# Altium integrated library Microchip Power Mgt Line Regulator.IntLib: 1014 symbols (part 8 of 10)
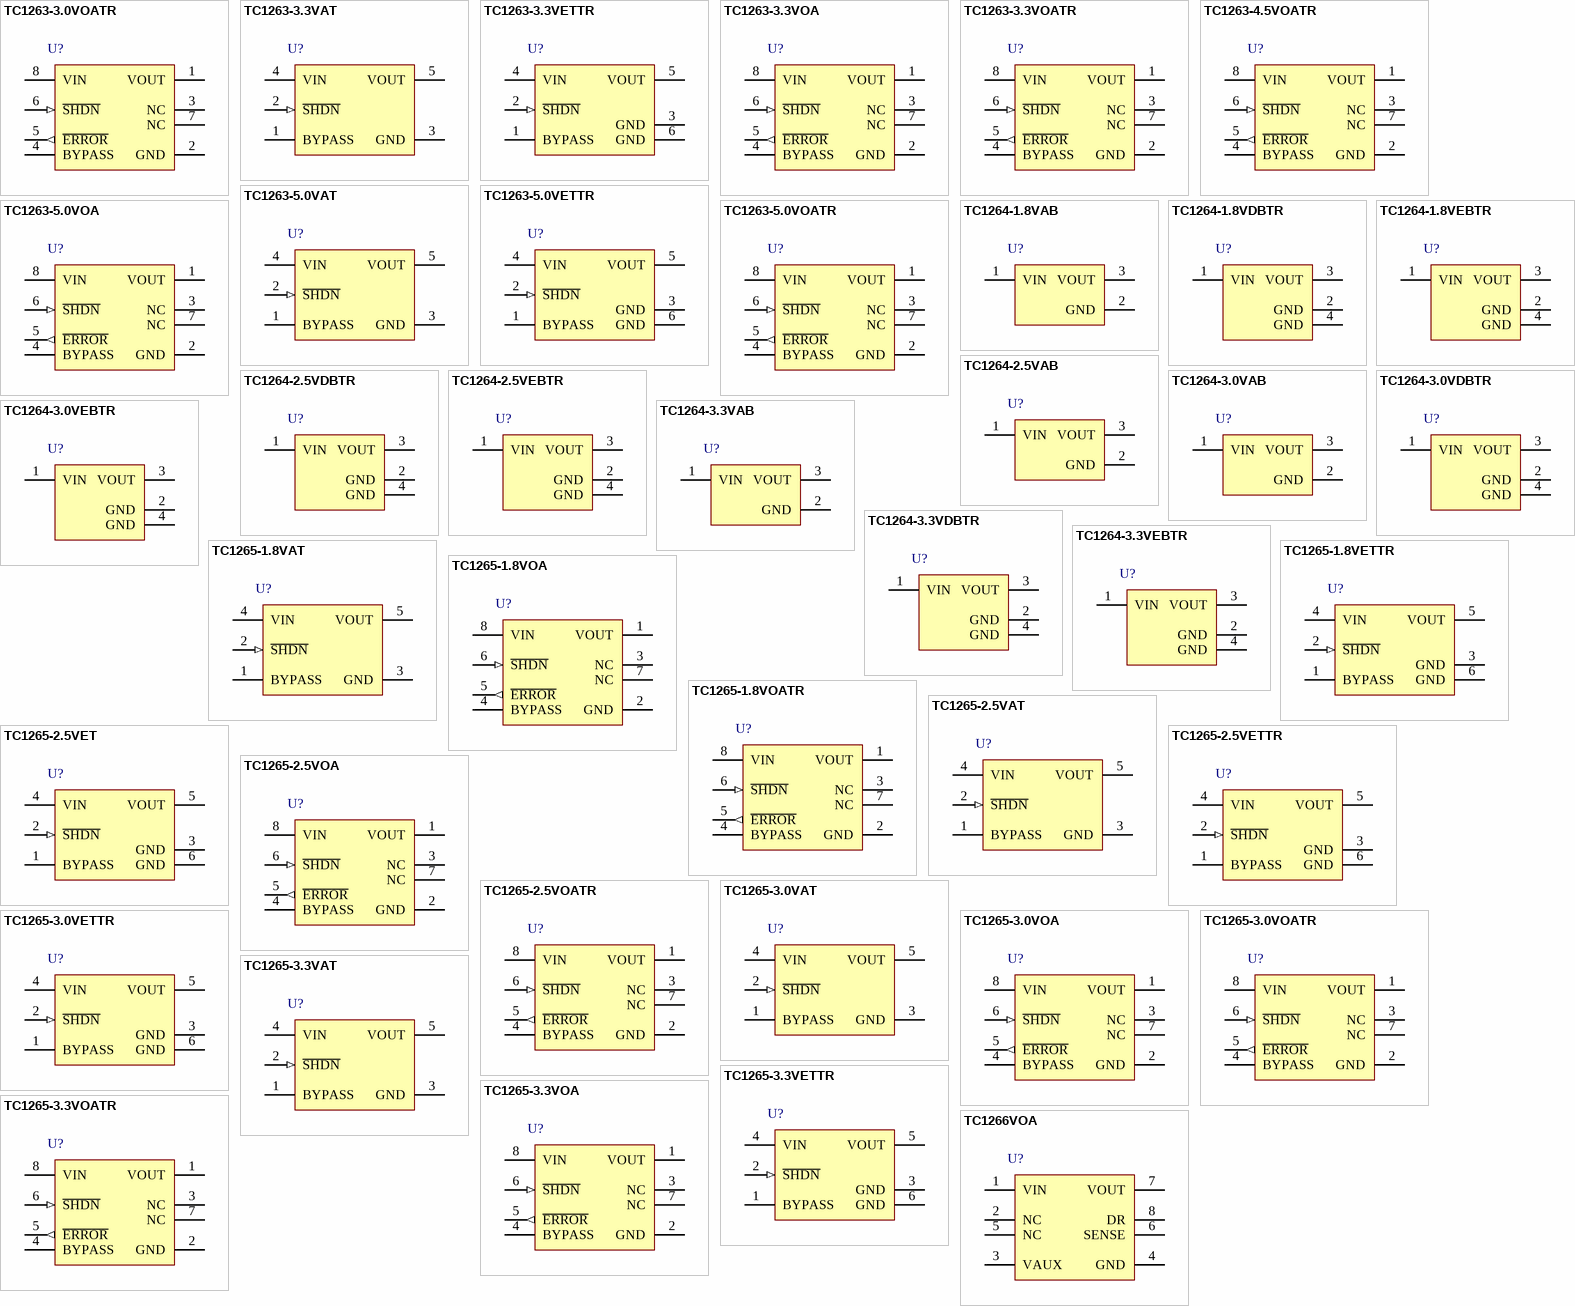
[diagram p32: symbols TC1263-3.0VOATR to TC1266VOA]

## TC1263-3.3VOA
designator U?
500mA Fixed Output, CMOS LDO with Shutdown, 8-Pin SOIC 150mil, Extended Temperature
footprint SOIC-OA8_N (SOIC, 8-Leads, Body 4.9x3.9mm, Pitch 1.27mm, IPC Medium Density)
footprint SOIC-OA8_L (SOIC, 8-Leads, Body 4.9x3.9mm, Pitch 1.27mm, IPC High Density)
footprint SOIC-OA8_M (SOIC, 8-Leads, Body 4.9x3.9mm, Pitch 1.27mm, IPC Low Density)
pins: 1 VOUT (power), 2 GND (power), 3 NC, 4 BYPASS, 5 ~{ERROR} (out), 6 ~{SHDN} (in), 7 NC, 8 VIN (power)

## TC1263-3.3VOATR
designator U?
500mA Fixed Output, CMOS LDO with Shutdown, 8-Pin SOIC 150mil, Extended Temperature, Tape and Reel
footprint SOIC-OA8_N (SOIC, 8-Leads, Body 4.9x3.9mm, Pitch 1.27mm, IPC Medium Density)
footprint SOIC-OA8_L (SOIC, 8-Leads, Body 4.9x3.9mm, Pitch 1.27mm, IPC High Density)
footprint SOIC-OA8_M (SOIC, 8-Leads, Body 4.9x3.9mm, Pitch 1.27mm, IPC Low Density)
pins: 1 VOUT (power), 2 GND (power), 3 NC, 4 BYPASS, 5 ~{ERROR} (out), 6 ~{SHDN} (in), 7 NC, 8 VIN (power)

## TC1263-4.5VOATR
designator U?
500mA Fixed Output, CMOS LDO with Shutdown, 8-Pin SOIC 150mil, Extended Temperature, Tape and Reel
footprint SOIC-OA8_N (SOIC, 8-Leads, Body 4.9x3.9mm, Pitch 1.27mm, IPC Medium Density)
footprint SOIC-OA8_L (SOIC, 8-Leads, Body 4.9x3.9mm, Pitch 1.27mm, IPC High Density)
footprint SOIC-OA8_M (SOIC, 8-Leads, Body 4.9x3.9mm, Pitch 1.27mm, IPC Low Density)
pins: 1 VOUT (power), 2 GND (power), 3 NC, 4 BYPASS, 5 ~{ERROR} (out), 6 ~{SHDN} (in), 7 NC, 8 VIN (power)

## TC1263-5.0VAT
designator U?
500mA Fixed Output, CMOS LDO with Shutdown, 5-Pin TO-220, Extended Temperature
footprint TO-220-AT5 (TO, Thru-Hole, Vertical, Heatsink Mounted; 5 In-Line Leads; Pitch 1.70 mm)
pins: 1 BYPASS, 2 ~{SHDN} (in), 3 GND (power), 4 VIN (power), 5 VOUT (power)

## TC1263-5.0VETTR
designator U?
500mA Fixed Output, CMOS LDO with Shutdown, 5-Pin DDPAK, Extended Temperature, Tape and Reel
footprint DDPAK-ET5_N (D2-PAK, 6-Leads, Body 9x10.2mm, Pitch 1.7mm, Lead Span 14.9mm, IPC Medium Density)
footprint DDPAK-ET5_L (D2-PAK, 6-Leads, Body 9x10.2mm, Pitch 1.7mm, Lead Span 14.9mm, IPC High Density)
footprint DDPAK-ET5_M (D2-PAK, 6-Leads, Body 9x10.2mm, Pitch 1.7mm, Lead Span 14.9mm, IPC Low Density)
pins: 1 BYPASS, 2 ~{SHDN} (in), 3 GND (power), 4 VIN (power), 5 VOUT (power), 6 GND (power)

## TC1263-5.0VOA
designator U?
500mA Fixed Output, CMOS LDO with Shutdown, 8-Pin SOIC 150mil, Extended Temperature
footprint SOIC-OA8_N (SOIC, 8-Leads, Body 4.9x3.9mm, Pitch 1.27mm, IPC Medium Density)
footprint SOIC-OA8_L (SOIC, 8-Leads, Body 4.9x3.9mm, Pitch 1.27mm, IPC High Density)
footprint SOIC-OA8_M (SOIC, 8-Leads, Body 4.9x3.9mm, Pitch 1.27mm, IPC Low Density)
pins: 1 VOUT (power), 2 GND (power), 3 NC, 4 BYPASS, 5 ~{ERROR} (out), 6 ~{SHDN} (in), 7 NC, 8 VIN (power)

## TC1263-5.0VOATR
designator U?
500mA Fixed Output, CMOS LDO with Shutdown, 8-Pin SOIC 150mil, Extended Temperature, Tape and Reel
footprint SOIC-OA8_N (SOIC, 8-Leads, Body 4.9x3.9mm, Pitch 1.27mm, IPC Medium Density)
footprint SOIC-OA8_L (SOIC, 8-Leads, Body 4.9x3.9mm, Pitch 1.27mm, IPC High Density)
footprint SOIC-OA8_M (SOIC, 8-Leads, Body 4.9x3.9mm, Pitch 1.27mm, IPC Low Density)
pins: 1 VOUT (power), 2 GND (power), 3 NC, 4 BYPASS, 5 ~{ERROR} (out), 6 ~{SHDN} (in), 7 NC, 8 VIN (power)

## TC1264-1.8VAB
designator U?
800 mA Fixed-Output CMOS LDO with Shutdown, 3-Pin TO-220, Extended Temperature
footprint TO-220-AB3 (TO, Thru-Hole, Vertical, Heatsink Mounted; 3 In-Line Leads; Pitch 2.54 mm)
pins: 1 VIN (power), 2 GND (power), 3 VOUT (power)

## TC1264-1.8VDBTR
designator U?
800 mA Fixed-Output CMOS LDO with Shutdown, 3-Pin SOT-223, Extended Temperature, Tape and Reel
footprint SOT-223-DB3_N (SOT223, 4-Leads, Body 6.5x3.5mm, Pitch 2.3mm, Lead Span 7mm, IPC Medium Density)
footprint SOT-223-DB3_L (SOT223, 4-Leads, Body 6.5x3.5mm, Pitch 2.3mm, Lead Span 7mm, IPC High Density)
footprint SOT-223-DB3_M (SOT223, 4-Leads, Body 6.5x3.5mm, Pitch 2.3mm, Lead Span 7mm, IPC Low Density)
pins: 1 VIN (power), 2 GND (power), 3 VOUT (power), 4 GND (power)

## TC1264-1.8VEBTR
designator U?
800 mA Fixed-Output CMOS LDO with Shutdown, 3-Pin DDPAK, Extended Temperature, Tape and Reel
footprint DDPAK-EB3_N (D2-PAK, 4-Leads, Body 9x10.2mm, Pitch 2.54mm, Lead Span 14.9mm, IPC Medium Density)
footprint DDPAK-EB3_L (D2-PAK, 4-Leads, Body 9x10.2mm, Pitch 2.54mm, Lead Span 14.9mm, IPC High Density)
footprint DDPAK-EB3_M (D2-PAK, 4-Leads, Body 9x10.2mm, Pitch 2.54mm, Lead Span 14.9mm, IPC Low Density)
pins: 1 VIN (power), 2 GND (power), 3 VOUT (power), 4 GND (power)

## TC1264-2.5VAB
designator U?
800 mA Fixed-Output CMOS LDO with Shutdown, 3-Pin TO-220, Extended Temperature
footprint TO-220-AB3 (TO, Thru-Hole, Vertical, Heatsink Mounted; 3 In-Line Leads; Pitch 2.54 mm)
pins: 1 VIN (power), 2 GND (power), 3 VOUT (power)

## TC1264-2.5VDBTR
designator U?
800 mA Fixed-Output CMOS LDO with Shutdown, 3-Pin SOT-223, Extended Temperature, Tape and Reel
footprint SOT-223-DB3_N (SOT223, 4-Leads, Body 6.5x3.5mm, Pitch 2.3mm, Lead Span 7mm, IPC Medium Density)
footprint SOT-223-DB3_L (SOT223, 4-Leads, Body 6.5x3.5mm, Pitch 2.3mm, Lead Span 7mm, IPC High Density)
footprint SOT-223-DB3_M (SOT223, 4-Leads, Body 6.5x3.5mm, Pitch 2.3mm, Lead Span 7mm, IPC Low Density)
pins: 1 VIN (power), 2 GND (power), 3 VOUT (power), 4 GND (power)

## TC1264-2.5VEBTR
designator U?
800 mA Fixed-Output CMOS LDO with Shutdown, 3-Pin DDPAK, Extended Temperature, Tape and Reel
footprint DDPAK-EB3_N (D2-PAK, 4-Leads, Body 9x10.2mm, Pitch 2.54mm, Lead Span 14.9mm, IPC Medium Density)
footprint DDPAK-EB3_L (D2-PAK, 4-Leads, Body 9x10.2mm, Pitch 2.54mm, Lead Span 14.9mm, IPC High Density)
footprint DDPAK-EB3_M (D2-PAK, 4-Leads, Body 9x10.2mm, Pitch 2.54mm, Lead Span 14.9mm, IPC Low Density)
pins: 1 VIN (power), 2 GND (power), 3 VOUT (power), 4 GND (power)

## TC1264-3.0VAB
designator U?
800 mA Fixed-Output CMOS LDO with Shutdown, 3-Pin TO-220, Extended Temperature
footprint TO-220-AB3 (TO, Thru-Hole, Vertical, Heatsink Mounted; 3 In-Line Leads; Pitch 2.54 mm)
pins: 1 VIN (power), 2 GND (power), 3 VOUT (power)

## TC1264-3.0VDBTR
designator U?
800 mA Fixed-Output CMOS LDO with Shutdown, 3-Pin SOT-223, Extended Temperature, Tape and Reel
footprint SOT-223-DB3_N (SOT223, 4-Leads, Body 6.5x3.5mm, Pitch 2.3mm, Lead Span 7mm, IPC Medium Density)
footprint SOT-223-DB3_L (SOT223, 4-Leads, Body 6.5x3.5mm, Pitch 2.3mm, Lead Span 7mm, IPC High Density)
footprint SOT-223-DB3_M (SOT223, 4-Leads, Body 6.5x3.5mm, Pitch 2.3mm, Lead Span 7mm, IPC Low Density)
pins: 1 VIN (power), 2 GND (power), 3 VOUT (power), 4 GND (power)

## TC1264-3.0VEBTR
designator U?
800 mA Fixed-Output CMOS LDO with Shutdown, 3-Pin DDPAK, Extended Temperature, Tape and Reel
footprint DDPAK-EB3_N (D2-PAK, 4-Leads, Body 9x10.2mm, Pitch 2.54mm, Lead Span 14.9mm, IPC Medium Density)
footprint DDPAK-EB3_L (D2-PAK, 4-Leads, Body 9x10.2mm, Pitch 2.54mm, Lead Span 14.9mm, IPC High Density)
footprint DDPAK-EB3_M (D2-PAK, 4-Leads, Body 9x10.2mm, Pitch 2.54mm, Lead Span 14.9mm, IPC Low Density)
pins: 1 VIN (power), 2 GND (power), 3 VOUT (power), 4 GND (power)

## TC1264-3.3VAB
designator U?
800 mA Fixed-Output CMOS LDO with Shutdown, 3-Pin TO-220, Extended Temperature
footprint TO-220-AB3 (TO, Thru-Hole, Vertical, Heatsink Mounted; 3 In-Line Leads; Pitch 2.54 mm)
pins: 1 VIN (power), 2 GND (power), 3 VOUT (power)

## TC1264-3.3VDBTR
designator U?
800 mA Fixed-Output CMOS LDO with Shutdown, 3-Pin SOT-223, Extended Temperature, Tape and Reel
footprint SOT-223-DB3_N (SOT223, 4-Leads, Body 6.5x3.5mm, Pitch 2.3mm, Lead Span 7mm, IPC Medium Density)
footprint SOT-223-DB3_L (SOT223, 4-Leads, Body 6.5x3.5mm, Pitch 2.3mm, Lead Span 7mm, IPC High Density)
footprint SOT-223-DB3_M (SOT223, 4-Leads, Body 6.5x3.5mm, Pitch 2.3mm, Lead Span 7mm, IPC Low Density)
pins: 1 VIN (power), 2 GND (power), 3 VOUT (power), 4 GND (power)

## TC1264-3.3VEBTR
designator U?
800 mA Fixed-Output CMOS LDO with Shutdown, 3-Pin DDPAK, Extended Temperature, Tape and Reel
footprint DDPAK-EB3_N (D2-PAK, 4-Leads, Body 9x10.2mm, Pitch 2.54mm, Lead Span 14.9mm, IPC Medium Density)
footprint DDPAK-EB3_L (D2-PAK, 4-Leads, Body 9x10.2mm, Pitch 2.54mm, Lead Span 14.9mm, IPC High Density)
footprint DDPAK-EB3_M (D2-PAK, 4-Leads, Body 9x10.2mm, Pitch 2.54mm, Lead Span 14.9mm, IPC Low Density)
pins: 1 VIN (power), 2 GND (power), 3 VOUT (power), 4 GND (power)

## TC1265-1.8VAT
designator U?
800 mA Fixed-Output CMOS LDO with Shutdown, 5-Pin TO-220, Extended Temperature
footprint TO-220-AT5 (TO, Thru-Hole, Vertical, Heatsink Mounted; 5 In-Line Leads; Pitch 1.70 mm)
pins: 1 BYPASS, 2 ~{SHDN} (in), 3 GND (power), 4 VIN (power), 5 VOUT (power)

## TC1265-1.8VETTR
designator U?
800 mA Fixed-Output CMOS LDO with Shutdown, 5-Pin DDPAK, Extended Temperature, Tape and Reel
footprint DDPAK-ET5_N (D2-PAK, 6-Leads, Body 9x10.2mm, Pitch 1.7mm, Lead Span 14.9mm, IPC Medium Density)
footprint DDPAK-ET5_L (D2-PAK, 6-Leads, Body 9x10.2mm, Pitch 1.7mm, Lead Span 14.9mm, IPC High Density)
footprint DDPAK-ET5_M (D2-PAK, 6-Leads, Body 9x10.2mm, Pitch 1.7mm, Lead Span 14.9mm, IPC Low Density)
pins: 1 BYPASS, 2 ~{SHDN} (in), 3 GND (power), 4 VIN (power), 5 VOUT (power), 6 GND (power)

## TC1265-1.8VOA
designator U?
800 mA Fixed-Output CMOS LDO with Shutdown, 8-Pin SOIC 150mil, Extended Temperature
footprint SOIC-OA8_N (SOIC, 8-Leads, Body 4.9x3.9mm, Pitch 1.27mm, IPC Medium Density)
footprint SOIC-OA8_L (SOIC, 8-Leads, Body 4.9x3.9mm, Pitch 1.27mm, IPC High Density)
footprint SOIC-OA8_M (SOIC, 8-Leads, Body 4.9x3.9mm, Pitch 1.27mm, IPC Low Density)
pins: 1 VOUT (power), 2 GND (power), 3 NC, 4 BYPASS, 5 ~{ERROR} (out), 6 ~{SHDN} (in), 7 NC, 8 VIN (power)

## TC1265-1.8VOATR
designator U?
800 mA Fixed-Output CMOS LDO with Shutdown, 8-Pin SOIC 150mil, Extended Temperature, Tape and Reel
footprint SOIC-OA8_N (SOIC, 8-Leads, Body 4.9x3.9mm, Pitch 1.27mm, IPC Medium Density)
footprint SOIC-OA8_L (SOIC, 8-Leads, Body 4.9x3.9mm, Pitch 1.27mm, IPC High Density)
footprint SOIC-OA8_M (SOIC, 8-Leads, Body 4.9x3.9mm, Pitch 1.27mm, IPC Low Density)
pins: 1 VOUT (power), 2 GND (power), 3 NC, 4 BYPASS, 5 ~{ERROR} (out), 6 ~{SHDN} (in), 7 NC, 8 VIN (power)

## TC1265-2.5VAT
designator U?
800 mA Fixed-Output CMOS LDO with Shutdown, 5-Pin TO-220, Extended Temperature
footprint TO-220-AT5 (TO, Thru-Hole, Vertical, Heatsink Mounted; 5 In-Line Leads; Pitch 1.70 mm)
pins: 1 BYPASS, 2 ~{SHDN} (in), 3 GND (power), 4 VIN (power), 5 VOUT (power)

## TC1265-2.5VET
designator U?
800 mA Fixed-Output CMOS LDO with Shutdown, 5-Pin DDPAK, Extended Temperature
footprint DDPAK-ET5_N (D2-PAK, 6-Leads, Body 9x10.2mm, Pitch 1.7mm, Lead Span 14.9mm, IPC Medium Density)
footprint DDPAK-ET5_L (D2-PAK, 6-Leads, Body 9x10.2mm, Pitch 1.7mm, Lead Span 14.9mm, IPC High Density)
footprint DDPAK-ET5_M (D2-PAK, 6-Leads, Body 9x10.2mm, Pitch 1.7mm, Lead Span 14.9mm, IPC Low Density)
pins: 1 BYPASS, 2 ~{SHDN} (in), 3 GND (power), 4 VIN (power), 5 VOUT (power), 6 GND (power)

## TC1265-2.5VETTR
designator U?
800 mA Fixed-Output CMOS LDO with Shutdown, 5-Pin DDPAK, Extended Temperature, Tape and Reel
footprint DDPAK-ET5_N (D2-PAK, 6-Leads, Body 9x10.2mm, Pitch 1.7mm, Lead Span 14.9mm, IPC Medium Density)
footprint DDPAK-ET5_L (D2-PAK, 6-Leads, Body 9x10.2mm, Pitch 1.7mm, Lead Span 14.9mm, IPC High Density)
footprint DDPAK-ET5_M (D2-PAK, 6-Leads, Body 9x10.2mm, Pitch 1.7mm, Lead Span 14.9mm, IPC Low Density)
pins: 1 BYPASS, 2 ~{SHDN} (in), 3 GND (power), 4 VIN (power), 5 VOUT (power), 6 GND (power)

## TC1265-2.5VOA
designator U?
800 mA Fixed-Output CMOS LDO with Shutdown, 8-Pin SOIC 150mil, Extended Temperature
footprint SOIC-OA8_N (SOIC, 8-Leads, Body 4.9x3.9mm, Pitch 1.27mm, IPC Medium Density)
footprint SOIC-OA8_L (SOIC, 8-Leads, Body 4.9x3.9mm, Pitch 1.27mm, IPC High Density)
footprint SOIC-OA8_M (SOIC, 8-Leads, Body 4.9x3.9mm, Pitch 1.27mm, IPC Low Density)
pins: 1 VOUT (power), 2 GND (power), 3 NC, 4 BYPASS, 5 ~{ERROR} (out), 6 ~{SHDN} (in), 7 NC, 8 VIN (power)

## TC1265-2.5VOATR
designator U?
800 mA Fixed-Output CMOS LDO with Shutdown, 8-Pin SOIC 150mil, Extended Temperature, Tape and Reel
footprint SOIC-OA8_N (SOIC, 8-Leads, Body 4.9x3.9mm, Pitch 1.27mm, IPC Medium Density)
footprint SOIC-OA8_L (SOIC, 8-Leads, Body 4.9x3.9mm, Pitch 1.27mm, IPC High Density)
footprint SOIC-OA8_M (SOIC, 8-Leads, Body 4.9x3.9mm, Pitch 1.27mm, IPC Low Density)
pins: 1 VOUT (power), 2 GND (power), 3 NC, 4 BYPASS, 5 ~{ERROR} (out), 6 ~{SHDN} (in), 7 NC, 8 VIN (power)

## TC1265-3.0VAT
designator U?
800 mA Fixed-Output CMOS LDO with Shutdown, 5-Pin TO-220, Extended Temperature
footprint TO-220-AT5 (TO, Thru-Hole, Vertical, Heatsink Mounted; 5 In-Line Leads; Pitch 1.70 mm)
pins: 1 BYPASS, 2 ~{SHDN} (in), 3 GND (power), 4 VIN (power), 5 VOUT (power)

## TC1265-3.0VETTR
designator U?
800 mA Fixed-Output CMOS LDO with Shutdown, 5-Pin DDPAK, Extended Temperature, Tape and Reel
footprint DDPAK-ET5_N (D2-PAK, 6-Leads, Body 9x10.2mm, Pitch 1.7mm, Lead Span 14.9mm, IPC Medium Density)
footprint DDPAK-ET5_L (D2-PAK, 6-Leads, Body 9x10.2mm, Pitch 1.7mm, Lead Span 14.9mm, IPC High Density)
footprint DDPAK-ET5_M (D2-PAK, 6-Leads, Body 9x10.2mm, Pitch 1.7mm, Lead Span 14.9mm, IPC Low Density)
pins: 1 BYPASS, 2 ~{SHDN} (in), 3 GND (power), 4 VIN (power), 5 VOUT (power), 6 GND (power)

## TC1265-3.0VOA
designator U?
800 mA Fixed-Output CMOS LDO with Shutdown, 8-Pin SOIC 150mil, Extended Temperature
footprint SOIC-OA8_N (SOIC, 8-Leads, Body 4.9x3.9mm, Pitch 1.27mm, IPC Medium Density)
footprint SOIC-OA8_L (SOIC, 8-Leads, Body 4.9x3.9mm, Pitch 1.27mm, IPC High Density)
footprint SOIC-OA8_M (SOIC, 8-Leads, Body 4.9x3.9mm, Pitch 1.27mm, IPC Low Density)
pins: 1 VOUT (power), 2 GND (power), 3 NC, 4 BYPASS, 5 ~{ERROR} (out), 6 ~{SHDN} (in), 7 NC, 8 VIN (power)

## TC1265-3.0VOATR
designator U?
800 mA Fixed-Output CMOS LDO with Shutdown, 8-Pin SOIC 150mil, Extended Temperature, Tape and Reel
footprint SOIC-OA8_N (SOIC, 8-Leads, Body 4.9x3.9mm, Pitch 1.27mm, IPC Medium Density)
footprint SOIC-OA8_L (SOIC, 8-Leads, Body 4.9x3.9mm, Pitch 1.27mm, IPC High Density)
footprint SOIC-OA8_M (SOIC, 8-Leads, Body 4.9x3.9mm, Pitch 1.27mm, IPC Low Density)
pins: 1 VOUT (power), 2 GND (power), 3 NC, 4 BYPASS, 5 ~{ERROR} (out), 6 ~{SHDN} (in), 7 NC, 8 VIN (power)

## TC1265-3.3VAT
designator U?
800 mA Fixed-Output CMOS LDO with Shutdown, 5-Pin TO-220, Extended Temperature
footprint TO-220-AT5 (TO, Thru-Hole, Vertical, Heatsink Mounted; 5 In-Line Leads; Pitch 1.70 mm)
pins: 1 BYPASS, 2 ~{SHDN} (in), 3 GND (power), 4 VIN (power), 5 VOUT (power)

## TC1265-3.3VETTR
designator U?
800 mA Fixed-Output CMOS LDO with Shutdown, 5-Pin DDPAK, Extended Temperature, Tape and Reel
footprint DDPAK-ET5_N (D2-PAK, 6-Leads, Body 9x10.2mm, Pitch 1.7mm, Lead Span 14.9mm, IPC Medium Density)
footprint DDPAK-ET5_L (D2-PAK, 6-Leads, Body 9x10.2mm, Pitch 1.7mm, Lead Span 14.9mm, IPC High Density)
footprint DDPAK-ET5_M (D2-PAK, 6-Leads, Body 9x10.2mm, Pitch 1.7mm, Lead Span 14.9mm, IPC Low Density)
pins: 1 BYPASS, 2 ~{SHDN} (in), 3 GND (power), 4 VIN (power), 5 VOUT (power), 6 GND (power)

## TC1265-3.3VOA
designator U?
800 mA Fixed-Output CMOS LDO with Shutdown, 8-Pin SOIC 150mil, Extended Temperature
footprint SOIC-OA8_N (SOIC, 8-Leads, Body 4.9x3.9mm, Pitch 1.27mm, IPC Medium Density)
footprint SOIC-OA8_L (SOIC, 8-Leads, Body 4.9x3.9mm, Pitch 1.27mm, IPC High Density)
footprint SOIC-OA8_M (SOIC, 8-Leads, Body 4.9x3.9mm, Pitch 1.27mm, IPC Low Density)
pins: 1 VOUT (power), 2 GND (power), 3 NC, 4 BYPASS, 5 ~{ERROR} (out), 6 ~{SHDN} (in), 7 NC, 8 VIN (power)

## TC1265-3.3VOATR
designator U?
800 mA Fixed-Output CMOS LDO with Shutdown, 8-Pin SOIC 150mil, Extended Temperature, Tape and Reel
footprint SOIC-OA8_N (SOIC, 8-Leads, Body 4.9x3.9mm, Pitch 1.27mm, IPC Medium Density)
footprint SOIC-OA8_L (SOIC, 8-Leads, Body 4.9x3.9mm, Pitch 1.27mm, IPC High Density)
footprint SOIC-OA8_M (SOIC, 8-Leads, Body 4.9x3.9mm, Pitch 1.27mm, IPC Low Density)
pins: 1 VOUT (power), 2 GND (power), 3 NC, 4 BYPASS, 5 ~{ERROR} (out), 6 ~{SHDN} (in), 7 NC, 8 VIN (power)

## TC1266VOA
designator U?
200mA PCI LDO, 8-Pin SOIC 150mil
footprint SOIC-OA8_N (SOIC, 8-Leads, Body 4.9x3.9mm, Pitch 1.27mm, IPC Medium Density)
footprint SOIC-OA8_L (SOIC, 8-Leads, Body 4.9x3.9mm, Pitch 1.27mm, IPC High Density)
footprint SOIC-OA8_M (SOIC, 8-Leads, Body 4.9x3.9mm, Pitch 1.27mm, IPC Low Density)
pins: 1 VIN (power), 2 NC, 3 VAUX (power), 4 GND (power), 5 NC, 6 SENSE, 7 VOUT (power), 8 DR

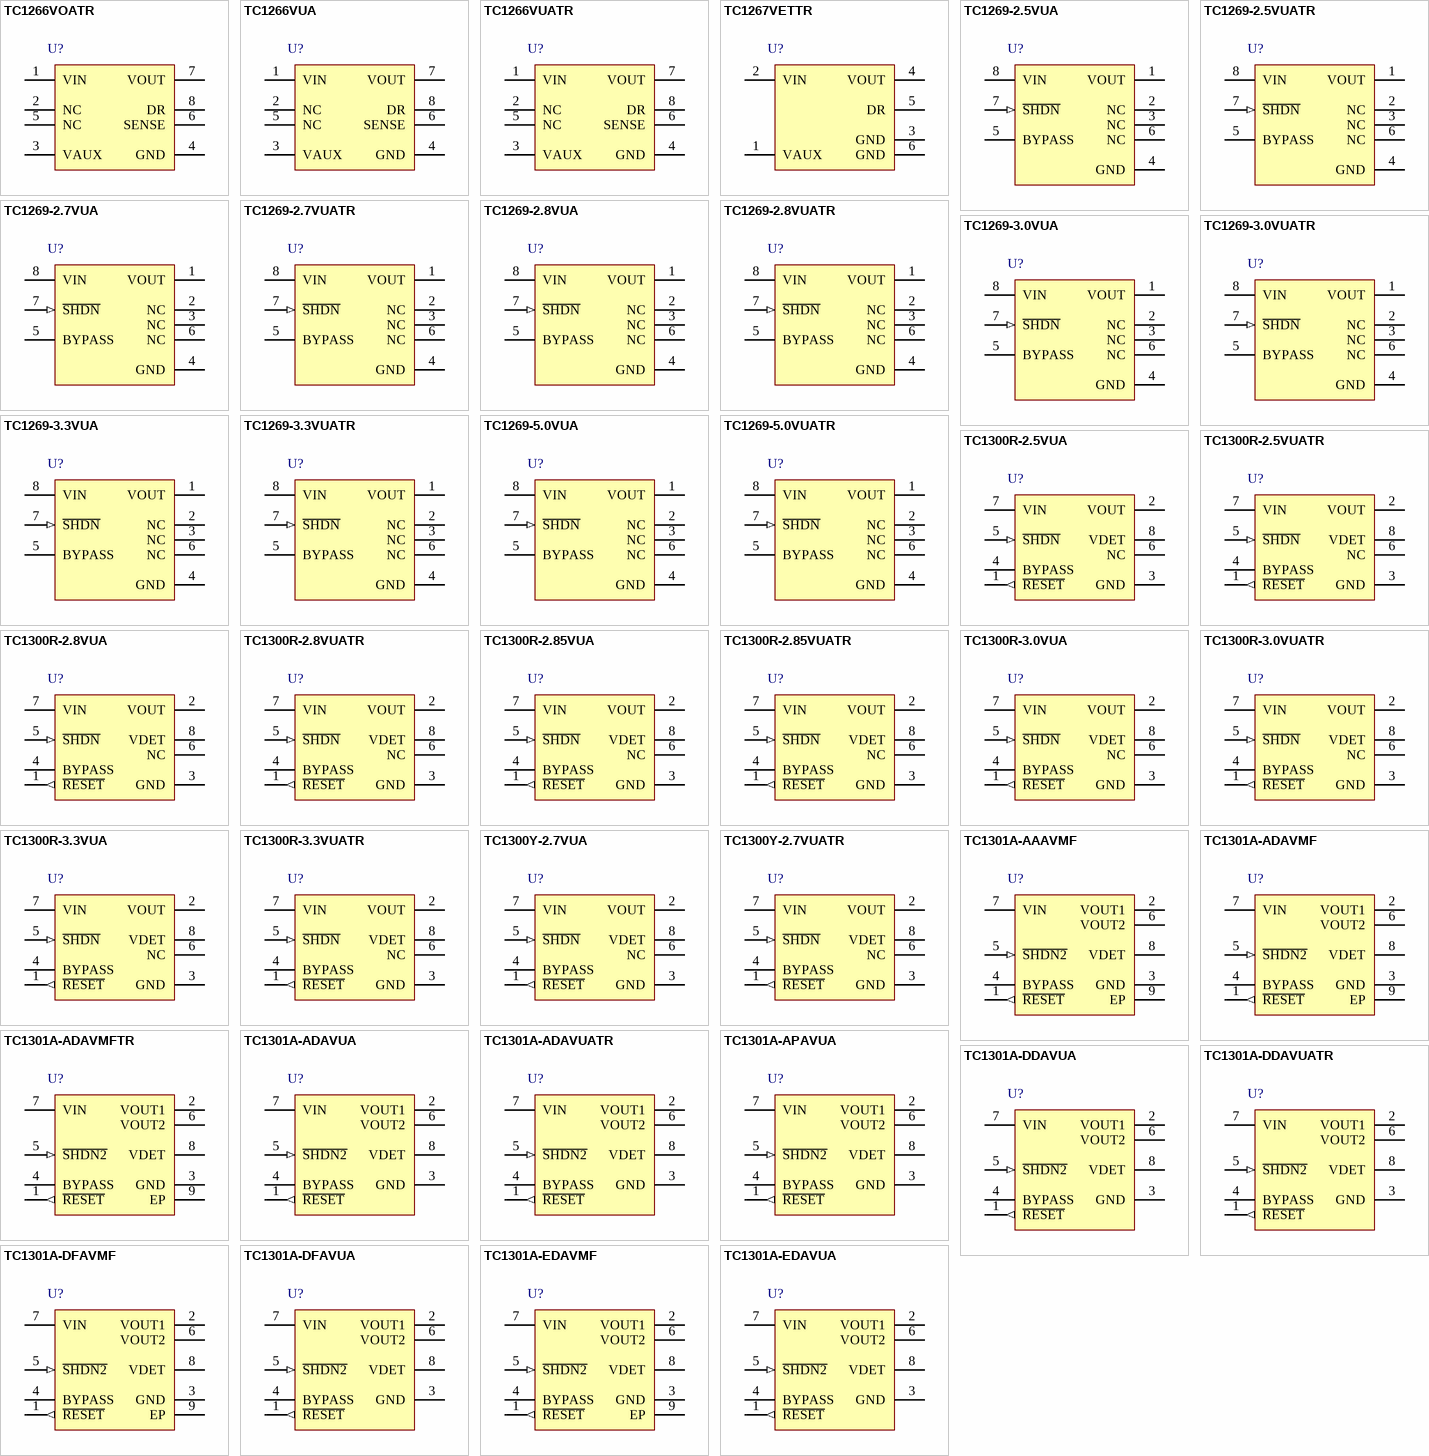
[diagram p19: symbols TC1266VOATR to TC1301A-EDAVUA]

## TC1266VOATR
designator U?
200mA PCI LDO, 8-Pin SOIC 150mil, Commercial Temperature, Tape and Reel
footprint SOIC-OA8_N (SOIC, 8-Leads, Body 4.9x3.9mm, Pitch 1.27mm, IPC Medium Density)
footprint SOIC-OA8_L (SOIC, 8-Leads, Body 4.9x3.9mm, Pitch 1.27mm, IPC High Density)
footprint SOIC-OA8_M (SOIC, 8-Leads, Body 4.9x3.9mm, Pitch 1.27mm, IPC Low Density)
pins: 1 VIN (power), 2 NC, 3 VAUX (power), 4 GND (power), 5 NC, 6 SENSE, 7 VOUT (power), 8 DR

## TC1266VUA
designator U?
200mA PCI LDO, 8-Pin MSOP
footprint MSOP-UA8_N (TSOP, 8-Leads, Body 3x3mm, Pitch 0.65mm, IPC Medium Density)
footprint MSOP-UA8_L (TSOP, 8-Leads, Body 3x3mm, Pitch 0.65mm, IPC High Density)
footprint MSOP-UA8_M (TSOP, 8-Leads, Body 3x3mm, Pitch 0.65mm, IPC Low Density)
pins: 1 VIN (power), 2 NC, 3 VAUX (power), 4 GND (power), 5 NC, 6 SENSE, 7 VOUT (power), 8 DR

## TC1266VUATR
designator U?
200mA PCI LDO, 8-Pin MSOP, Commercial Temperature, Tape and Reel
footprint MSOP-UA8_N (TSOP, 8-Leads, Body 3x3mm, Pitch 0.65mm, IPC Medium Density)
footprint MSOP-UA8_L (TSOP, 8-Leads, Body 3x3mm, Pitch 0.65mm, IPC High Density)
footprint MSOP-UA8_M (TSOP, 8-Leads, Body 3x3mm, Pitch 0.65mm, IPC Low Density)
pins: 1 VIN (power), 2 NC, 3 VAUX (power), 4 GND (power), 5 NC, 6 SENSE, 7 VOUT (power), 8 DR

## TC1267VETTR
designator U?
400mA PCI LDO, 5-Pin DDPAK, Commercial Temperature, Tape and Reel
footprint DDPAK-ET5_N (D2-PAK, 6-Leads, Body 9x10.2mm, Pitch 1.7mm, Lead Span 14.9mm, IPC Medium Density)
footprint DDPAK-ET5_L (D2-PAK, 6-Leads, Body 9x10.2mm, Pitch 1.7mm, Lead Span 14.9mm, IPC High Density)
footprint DDPAK-ET5_M (D2-PAK, 6-Leads, Body 9x10.2mm, Pitch 1.7mm, Lead Span 14.9mm, IPC Low Density)
pins: 1 VAUX (power), 2 VIN (power), 3 GND (power), 4 VOUT (power), 5 DR, 6 GND (power)

## TC1269-2.5VUA
designator U?
300mA CMOS LDO with Shutdown and VREF Bypass, 8-Pin MSOP, Extended Temperature
footprint MSOP-UA8_N (TSOP, 8-Leads, Body 3x3mm, Pitch 0.65mm, IPC Medium Density)
footprint MSOP-UA8_L (TSOP, 8-Leads, Body 3x3mm, Pitch 0.65mm, IPC High Density)
footprint MSOP-UA8_M (TSOP, 8-Leads, Body 3x3mm, Pitch 0.65mm, IPC Low Density)
pins: 1 VOUT (power), 2 NC, 3 NC, 4 GND (power), 5 BYPASS, 6 NC, 7 ~{SHDN} (in), 8 VIN (power)

## TC1269-2.5VUATR
designator U?
300mA CMOS LDO with Shutdown and VREF Bypass, 8-Pin MSOP, Extended Temperature, Tape and Reel
footprint MSOP-UA8_N (TSOP, 8-Leads, Body 3x3mm, Pitch 0.65mm, IPC Medium Density)
footprint MSOP-UA8_L (TSOP, 8-Leads, Body 3x3mm, Pitch 0.65mm, IPC High Density)
footprint MSOP-UA8_M (TSOP, 8-Leads, Body 3x3mm, Pitch 0.65mm, IPC Low Density)
pins: 1 VOUT (power), 2 NC, 3 NC, 4 GND (power), 5 BYPASS, 6 NC, 7 ~{SHDN} (in), 8 VIN (power)

## TC1269-2.7VUA
designator U?
300mA CMOS LDO with Shutdown and VREF Bypass, 8-Pin MSOP, Extended Temperature
footprint MSOP-UA8_N (TSOP, 8-Leads, Body 3x3mm, Pitch 0.65mm, IPC Medium Density)
footprint MSOP-UA8_L (TSOP, 8-Leads, Body 3x3mm, Pitch 0.65mm, IPC High Density)
footprint MSOP-UA8_M (TSOP, 8-Leads, Body 3x3mm, Pitch 0.65mm, IPC Low Density)
pins: 1 VOUT (power), 2 NC, 3 NC, 4 GND (power), 5 BYPASS, 6 NC, 7 ~{SHDN} (in), 8 VIN (power)

## TC1269-2.7VUATR
designator U?
300mA CMOS LDO with Shutdown and VREF Bypass, 8-Pin MSOP, Extended Temperature, Tape and Reel
footprint MSOP-UA8_N (TSOP, 8-Leads, Body 3x3mm, Pitch 0.65mm, IPC Medium Density)
footprint MSOP-UA8_L (TSOP, 8-Leads, Body 3x3mm, Pitch 0.65mm, IPC High Density)
footprint MSOP-UA8_M (TSOP, 8-Leads, Body 3x3mm, Pitch 0.65mm, IPC Low Density)
pins: 1 VOUT (power), 2 NC, 3 NC, 4 GND (power), 5 BYPASS, 6 NC, 7 ~{SHDN} (in), 8 VIN (power)

## TC1269-2.8VUA
designator U?
300mA CMOS LDO with Shutdown and VREF Bypass, 8-Pin MSOP, Extended Temperature
footprint MSOP-UA8_N (TSOP, 8-Leads, Body 3x3mm, Pitch 0.65mm, IPC Medium Density)
footprint MSOP-UA8_L (TSOP, 8-Leads, Body 3x3mm, Pitch 0.65mm, IPC High Density)
footprint MSOP-UA8_M (TSOP, 8-Leads, Body 3x3mm, Pitch 0.65mm, IPC Low Density)
pins: 1 VOUT (power), 2 NC, 3 NC, 4 GND (power), 5 BYPASS, 6 NC, 7 ~{SHDN} (in), 8 VIN (power)

## TC1269-2.8VUATR
designator U?
300mA CMOS LDO with Shutdown and VREF Bypass, 8-Pin MSOP, Extended Temperature, Tape and Reel
footprint MSOP-UA8_N (TSOP, 8-Leads, Body 3x3mm, Pitch 0.65mm, IPC Medium Density)
footprint MSOP-UA8_L (TSOP, 8-Leads, Body 3x3mm, Pitch 0.65mm, IPC High Density)
footprint MSOP-UA8_M (TSOP, 8-Leads, Body 3x3mm, Pitch 0.65mm, IPC Low Density)
pins: 1 VOUT (power), 2 NC, 3 NC, 4 GND (power), 5 BYPASS, 6 NC, 7 ~{SHDN} (in), 8 VIN (power)

## TC1269-3.0VUA
designator U?
300mA CMOS LDO with Shutdown and VREF Bypass, 8-Pin MSOP, Extended Temperature
footprint MSOP-UA8_N (TSOP, 8-Leads, Body 3x3mm, Pitch 0.65mm, IPC Medium Density)
footprint MSOP-UA8_L (TSOP, 8-Leads, Body 3x3mm, Pitch 0.65mm, IPC High Density)
footprint MSOP-UA8_M (TSOP, 8-Leads, Body 3x3mm, Pitch 0.65mm, IPC Low Density)
pins: 1 VOUT (power), 2 NC, 3 NC, 4 GND (power), 5 BYPASS, 6 NC, 7 ~{SHDN} (in), 8 VIN (power)

## TC1269-3.0VUATR
designator U?
300mA CMOS LDO with Shutdown and VREF Bypass, 8-Pin MSOP, Extended Temperature, Tape and Reel
footprint MSOP-UA8_N (TSOP, 8-Leads, Body 3x3mm, Pitch 0.65mm, IPC Medium Density)
footprint MSOP-UA8_L (TSOP, 8-Leads, Body 3x3mm, Pitch 0.65mm, IPC High Density)
footprint MSOP-UA8_M (TSOP, 8-Leads, Body 3x3mm, Pitch 0.65mm, IPC Low Density)
pins: 1 VOUT (power), 2 NC, 3 NC, 4 GND (power), 5 BYPASS, 6 NC, 7 ~{SHDN} (in), 8 VIN (power)

## TC1269-3.3VUA
designator U?
300mA CMOS LDO with Shutdown and VREF Bypass, 8-Pin MSOP, Extended Temperature
footprint MSOP-UA8_N (TSOP, 8-Leads, Body 3x3mm, Pitch 0.65mm, IPC Medium Density)
footprint MSOP-UA8_L (TSOP, 8-Leads, Body 3x3mm, Pitch 0.65mm, IPC High Density)
footprint MSOP-UA8_M (TSOP, 8-Leads, Body 3x3mm, Pitch 0.65mm, IPC Low Density)
pins: 1 VOUT (power), 2 NC, 3 NC, 4 GND (power), 5 BYPASS, 6 NC, 7 ~{SHDN} (in), 8 VIN (power)

## TC1269-3.3VUATR
designator U?
300mA CMOS LDO with Shutdown and VREF Bypass, 8-Pin MSOP, Extended Temperature, Tape and Reel
footprint MSOP-UA8_N (TSOP, 8-Leads, Body 3x3mm, Pitch 0.65mm, IPC Medium Density)
footprint MSOP-UA8_L (TSOP, 8-Leads, Body 3x3mm, Pitch 0.65mm, IPC High Density)
footprint MSOP-UA8_M (TSOP, 8-Leads, Body 3x3mm, Pitch 0.65mm, IPC Low Density)
pins: 1 VOUT (power), 2 NC, 3 NC, 4 GND (power), 5 BYPASS, 6 NC, 7 ~{SHDN} (in), 8 VIN (power)

## TC1269-5.0VUA
designator U?
300mA CMOS LDO with Shutdown and VREF Bypass, 8-Pin MSOP, Extended Temperature
footprint MSOP-UA8_N (TSOP, 8-Leads, Body 3x3mm, Pitch 0.65mm, IPC Medium Density)
footprint MSOP-UA8_L (TSOP, 8-Leads, Body 3x3mm, Pitch 0.65mm, IPC High Density)
footprint MSOP-UA8_M (TSOP, 8-Leads, Body 3x3mm, Pitch 0.65mm, IPC Low Density)
pins: 1 VOUT (power), 2 NC, 3 NC, 4 GND (power), 5 BYPASS, 6 NC, 7 ~{SHDN} (in), 8 VIN (power)

## TC1269-5.0VUATR
designator U?
300mA CMOS LDO with Shutdown and VREF Bypass, 8-Pin MSOP, Extended Temperature, Tape and Reel
footprint MSOP-UA8_N (TSOP, 8-Leads, Body 3x3mm, Pitch 0.65mm, IPC Medium Density)
footprint MSOP-UA8_L (TSOP, 8-Leads, Body 3x3mm, Pitch 0.65mm, IPC High Density)
footprint MSOP-UA8_M (TSOP, 8-Leads, Body 3x3mm, Pitch 0.65mm, IPC Low Density)
pins: 1 VOUT (power), 2 NC, 3 NC, 4 GND (power), 5 BYPASS, 6 NC, 7 ~{SHDN} (in), 8 VIN (power)

## TC1300R-2.5VUA
designator U?
300 mA CMOS LDO with Shutdown, Bypass and Independent Delayed Reset Function, 8-Pin MSOP, Extended Temperature
footprint MSOP-UA8_N (TSOP, 8-Leads, Body 3x3mm, Pitch 0.65mm, IPC Medium Density)
footprint MSOP-UA8_L (TSOP, 8-Leads, Body 3x3mm, Pitch 0.65mm, IPC High Density)
footprint MSOP-UA8_M (TSOP, 8-Leads, Body 3x3mm, Pitch 0.65mm, IPC Low Density)
pins: 1 ~{RESET} (out), 2 VOUT (power), 3 GND (power), 4 BYPASS, 5 ~{SHDN} (in), 6 NC, 7 VIN (power), 8 VDET (power)

## TC1300R-2.5VUATR
designator U?
300 mA CMOS LDO with Shutdown, Bypass and Independent Delayed Reset Function, 8-Pin MSOP, Extended Temperature, Tape and Reel
footprint MSOP-UA8_N (TSOP, 8-Leads, Body 3x3mm, Pitch 0.65mm, IPC Medium Density)
footprint MSOP-UA8_L (TSOP, 8-Leads, Body 3x3mm, Pitch 0.65mm, IPC High Density)
footprint MSOP-UA8_M (TSOP, 8-Leads, Body 3x3mm, Pitch 0.65mm, IPC Low Density)
pins: 1 ~{RESET} (out), 2 VOUT (power), 3 GND (power), 4 BYPASS, 5 ~{SHDN} (in), 6 NC, 7 VIN (power), 8 VDET (power)

## TC1300R-2.8VUA
designator U?
300 mA CMOS LDO with Shutdown, Bypass and Independent Delayed Reset Function, 8-Pin MSOP, Extended Temperature
footprint MSOP-UA8_N (TSOP, 8-Leads, Body 3x3mm, Pitch 0.65mm, IPC Medium Density)
footprint MSOP-UA8_L (TSOP, 8-Leads, Body 3x3mm, Pitch 0.65mm, IPC High Density)
footprint MSOP-UA8_M (TSOP, 8-Leads, Body 3x3mm, Pitch 0.65mm, IPC Low Density)
pins: 1 ~{RESET} (out), 2 VOUT (power), 3 GND (power), 4 BYPASS, 5 ~{SHDN} (in), 6 NC, 7 VIN (power), 8 VDET (power)

## TC1300R-2.8VUATR
designator U?
300 mA CMOS LDO with Shutdown, Bypass and Independent Delayed Reset Function, 8-Pin MSOP, Extended Temperature, Tape and Reel
footprint MSOP-UA8_N (TSOP, 8-Leads, Body 3x3mm, Pitch 0.65mm, IPC Medium Density)
footprint MSOP-UA8_L (TSOP, 8-Leads, Body 3x3mm, Pitch 0.65mm, IPC High Density)
footprint MSOP-UA8_M (TSOP, 8-Leads, Body 3x3mm, Pitch 0.65mm, IPC Low Density)
pins: 1 ~{RESET} (out), 2 VOUT (power), 3 GND (power), 4 BYPASS, 5 ~{SHDN} (in), 6 NC, 7 VIN (power), 8 VDET (power)

## TC1300R-2.85VUA
designator U?
300 mA CMOS LDO with Shutdown, Bypass and Independent Delayed Reset Function, 8-Pin MSOP, Extended Temperature
footprint MSOP-UA8_N (TSOP, 8-Leads, Body 3x3mm, Pitch 0.65mm, IPC Medium Density)
footprint MSOP-UA8_L (TSOP, 8-Leads, Body 3x3mm, Pitch 0.65mm, IPC High Density)
footprint MSOP-UA8_M (TSOP, 8-Leads, Body 3x3mm, Pitch 0.65mm, IPC Low Density)
pins: 1 ~{RESET} (out), 2 VOUT (power), 3 GND (power), 4 BYPASS, 5 ~{SHDN} (in), 6 NC, 7 VIN (power), 8 VDET (power)

## TC1300R-2.85VUATR
designator U?
300 mA CMOS LDO with Shutdown, Bypass and Independent Delayed Reset Function, 8-Pin MSOP, Extended Temperature, Tape and Reel
footprint MSOP-UA8_N (TSOP, 8-Leads, Body 3x3mm, Pitch 0.65mm, IPC Medium Density)
footprint MSOP-UA8_L (TSOP, 8-Leads, Body 3x3mm, Pitch 0.65mm, IPC High Density)
footprint MSOP-UA8_M (TSOP, 8-Leads, Body 3x3mm, Pitch 0.65mm, IPC Low Density)
pins: 1 ~{RESET} (out), 2 VOUT (power), 3 GND (power), 4 BYPASS, 5 ~{SHDN} (in), 6 NC, 7 VIN (power), 8 VDET (power)

## TC1300R-3.0VUA
designator U?
300 mA CMOS LDO with Shutdown, Bypass and Independent Delayed Reset Function, 8-Pin MSOP, Extended Temperature
footprint MSOP-UA8_N (TSOP, 8-Leads, Body 3x3mm, Pitch 0.65mm, IPC Medium Density)
footprint MSOP-UA8_L (TSOP, 8-Leads, Body 3x3mm, Pitch 0.65mm, IPC High Density)
footprint MSOP-UA8_M (TSOP, 8-Leads, Body 3x3mm, Pitch 0.65mm, IPC Low Density)
pins: 1 ~{RESET} (out), 2 VOUT (power), 3 GND (power), 4 BYPASS, 5 ~{SHDN} (in), 6 NC, 7 VIN (power), 8 VDET (power)

## TC1300R-3.0VUATR
designator U?
300 mA CMOS LDO with Shutdown, Bypass and Independent Delayed Reset Function, 8-Pin MSOP, Extended Temperature, Tape and Reel
footprint MSOP-UA8_N (TSOP, 8-Leads, Body 3x3mm, Pitch 0.65mm, IPC Medium Density)
footprint MSOP-UA8_L (TSOP, 8-Leads, Body 3x3mm, Pitch 0.65mm, IPC High Density)
footprint MSOP-UA8_M (TSOP, 8-Leads, Body 3x3mm, Pitch 0.65mm, IPC Low Density)
pins: 1 ~{RESET} (out), 2 VOUT (power), 3 GND (power), 4 BYPASS, 5 ~{SHDN} (in), 6 NC, 7 VIN (power), 8 VDET (power)

## TC1300R-3.3VUA
designator U?
300 mA CMOS LDO with Shutdown, Bypass and Independent Delayed Reset Function, 8-Pin MSOP, Extended Temperature
footprint MSOP-UA8_N (TSOP, 8-Leads, Body 3x3mm, Pitch 0.65mm, IPC Medium Density)
footprint MSOP-UA8_L (TSOP, 8-Leads, Body 3x3mm, Pitch 0.65mm, IPC High Density)
footprint MSOP-UA8_M (TSOP, 8-Leads, Body 3x3mm, Pitch 0.65mm, IPC Low Density)
pins: 1 ~{RESET} (out), 2 VOUT (power), 3 GND (power), 4 BYPASS, 5 ~{SHDN} (in), 6 NC, 7 VIN (power), 8 VDET (power)

## TC1300R-3.3VUATR
designator U?
300 mA CMOS LDO with Shutdown, Bypass and Independent Delayed Reset Function, 8-Pin MSOP, Extended Temperature, Tape and Reel
footprint MSOP-UA8_N (TSOP, 8-Leads, Body 3x3mm, Pitch 0.65mm, IPC Medium Density)
footprint MSOP-UA8_L (TSOP, 8-Leads, Body 3x3mm, Pitch 0.65mm, IPC High Density)
footprint MSOP-UA8_M (TSOP, 8-Leads, Body 3x3mm, Pitch 0.65mm, IPC Low Density)
pins: 1 ~{RESET} (out), 2 VOUT (power), 3 GND (power), 4 BYPASS, 5 ~{SHDN} (in), 6 NC, 7 VIN (power), 8 VDET (power)

## TC1300Y-2.7VUA
designator U?
300 mA CMOS LDO with Shutdown, Bypass and Independent Delayed Reset Function, 8-Pin MSOP, Extended Temperature
footprint MSOP-UA8_N (TSOP, 8-Leads, Body 3x3mm, Pitch 0.65mm, IPC Medium Density)
footprint MSOP-UA8_L (TSOP, 8-Leads, Body 3x3mm, Pitch 0.65mm, IPC High Density)
footprint MSOP-UA8_M (TSOP, 8-Leads, Body 3x3mm, Pitch 0.65mm, IPC Low Density)
pins: 1 ~{RESET} (out), 2 VOUT (power), 3 GND (power), 4 BYPASS, 5 ~{SHDN} (in), 6 NC, 7 VIN (power), 8 VDET (power)

## TC1300Y-2.7VUATR
designator U?
300 mA CMOS LDO with Shutdown, Bypass and Independent Delayed Reset Function, 8-Pin MSOP, Extended Temperature, Tape and Reel
footprint MSOP-UA8_N (TSOP, 8-Leads, Body 3x3mm, Pitch 0.65mm, IPC Medium Density)
footprint MSOP-UA8_L (TSOP, 8-Leads, Body 3x3mm, Pitch 0.65mm, IPC High Density)
footprint MSOP-UA8_M (TSOP, 8-Leads, Body 3x3mm, Pitch 0.65mm, IPC Low Density)
pins: 1 ~{RESET} (out), 2 VOUT (power), 3 GND (power), 4 BYPASS, 5 ~{SHDN} (in), 6 NC, 7 VIN (power), 8 VDET (power)

## TC1301A-AAAVMF
designator U?
Dual LDO with Microcontroller Active-Low Reset Function, 8-Pin DFN, Extended Temperature
footprint DFN-MF8 (SON, 8-Leads, Body 3x3mm, Pitch 0.65mm, Microchip Recommended)
pins: 1 ~{RESET} (out), 2 VOUT1 (power), 3 GND (power), 4 BYPASS, 5 ~{SHDN2} (in), 6 VOUT2 (power), 7 VIN (power), 8 VDET (power), 9 EP (power)

## TC1301A-ADAVMF
designator U?
Dual LDO with Microcontroller Active-Low Reset Function, 8-Pin DFN, Extended Temperature
footprint DFN-MF8 (SON, 8-Leads, Body 3x3mm, Pitch 0.65mm, Microchip Recommended)
pins: 1 ~{RESET} (out), 2 VOUT1 (power), 3 GND (power), 4 BYPASS, 5 ~{SHDN2} (in), 6 VOUT2 (power), 7 VIN (power), 8 VDET (power), 9 EP (power)

## TC1301A-ADAVMFTR
designator U?
Dual LDO with Microcontroller Active-Low Reset Function, 8-Pin DFN, Extended Temperature, Tape and Reel
footprint DFN-MF8 (SON, 8-Leads, Body 3x3mm, Pitch 0.65mm, Microchip Recommended)
pins: 1 ~{RESET} (out), 2 VOUT1 (power), 3 GND (power), 4 BYPASS, 5 ~{SHDN2} (in), 6 VOUT2 (power), 7 VIN (power), 8 VDET (power), 9 EP (power)

## TC1301A-ADAVUA
designator U?
Dual LDO with Microcontroller Active-Low Reset Function, 8-Pin MSOP, Extended Temperature
footprint MSOP-UA8_N (TSOP, 8-Leads, Body 3x3mm, Pitch 0.65mm, IPC Medium Density)
footprint MSOP-UA8_L (TSOP, 8-Leads, Body 3x3mm, Pitch 0.65mm, IPC High Density)
footprint MSOP-UA8_M (TSOP, 8-Leads, Body 3x3mm, Pitch 0.65mm, IPC Low Density)
pins: 1 ~{RESET} (out), 2 VOUT1 (power), 3 GND (power), 4 BYPASS, 5 ~{SHDN2} (in), 6 VOUT2 (power), 7 VIN (power), 8 VDET (power)

## TC1301A-ADAVUATR
designator U?
Dual LDO with Microcontroller Active-Low Reset Function, 8-Pin MSOP, Extended Temperature, Tape and Reel
footprint MSOP-UA8_N (TSOP, 8-Leads, Body 3x3mm, Pitch 0.65mm, IPC Medium Density)
footprint MSOP-UA8_L (TSOP, 8-Leads, Body 3x3mm, Pitch 0.65mm, IPC High Density)
footprint MSOP-UA8_M (TSOP, 8-Leads, Body 3x3mm, Pitch 0.65mm, IPC Low Density)
pins: 1 ~{RESET} (out), 2 VOUT1 (power), 3 GND (power), 4 BYPASS, 5 ~{SHDN2} (in), 6 VOUT2 (power), 7 VIN (power), 8 VDET (power)

## TC1301A-APAVUA
designator U?
Dual LDO with Microcontroller Active-Low Reset Function, 8-Pin MSOP, Extended Temperature
footprint MSOP-UA8_N (TSOP, 8-Leads, Body 3x3mm, Pitch 0.65mm, IPC Medium Density)
footprint MSOP-UA8_L (TSOP, 8-Leads, Body 3x3mm, Pitch 0.65mm, IPC High Density)
footprint MSOP-UA8_M (TSOP, 8-Leads, Body 3x3mm, Pitch 0.65mm, IPC Low Density)
pins: 1 ~{RESET} (out), 2 VOUT1 (power), 3 GND (power), 4 BYPASS, 5 ~{SHDN2} (in), 6 VOUT2 (power), 7 VIN (power), 8 VDET (power)

## TC1301A-DDAVUA
designator U?
Dual LDO with Microcontroller Active-Low Reset Function, 8-Pin MSOP, Extended Temperature
footprint MSOP-UA8_N (TSOP, 8-Leads, Body 3x3mm, Pitch 0.65mm, IPC Medium Density)
footprint MSOP-UA8_L (TSOP, 8-Leads, Body 3x3mm, Pitch 0.65mm, IPC High Density)
footprint MSOP-UA8_M (TSOP, 8-Leads, Body 3x3mm, Pitch 0.65mm, IPC Low Density)
pins: 1 ~{RESET} (out), 2 VOUT1 (power), 3 GND (power), 4 BYPASS, 5 ~{SHDN2} (in), 6 VOUT2 (power), 7 VIN (power), 8 VDET (power)

## TC1301A-DDAVUATR
designator U?
Dual LDO with Microcontroller Active-Low Reset Function, 8-Pin MSOP, Extended Temperature, Tape and Reel
footprint MSOP-UA8_N (TSOP, 8-Leads, Body 3x3mm, Pitch 0.65mm, IPC Medium Density)
footprint MSOP-UA8_L (TSOP, 8-Leads, Body 3x3mm, Pitch 0.65mm, IPC High Density)
footprint MSOP-UA8_M (TSOP, 8-Leads, Body 3x3mm, Pitch 0.65mm, IPC Low Density)
pins: 1 ~{RESET} (out), 2 VOUT1 (power), 3 GND (power), 4 BYPASS, 5 ~{SHDN2} (in), 6 VOUT2 (power), 7 VIN (power), 8 VDET (power)

## TC1301A-DFAVMF
designator U?
Dual LDO with Microcontroller Active-Low Reset Function, 8-Pin DFN, Extended Temperature
footprint DFN-MF8 (SON, 8-Leads, Body 3x3mm, Pitch 0.65mm, Microchip Recommended)
pins: 1 ~{RESET} (out), 2 VOUT1 (power), 3 GND (power), 4 BYPASS, 5 ~{SHDN2} (in), 6 VOUT2 (power), 7 VIN (power), 8 VDET (power), 9 EP (power)

## TC1301A-DFAVUA
designator U?
Dual LDO with Microcontroller Active-Low Reset Function, 8-Pin MSOP, Extended Temperature
footprint MSOP-UA8_N (TSOP, 8-Leads, Body 3x3mm, Pitch 0.65mm, IPC Medium Density)
footprint MSOP-UA8_L (TSOP, 8-Leads, Body 3x3mm, Pitch 0.65mm, IPC High Density)
footprint MSOP-UA8_M (TSOP, 8-Leads, Body 3x3mm, Pitch 0.65mm, IPC Low Density)
pins: 1 ~{RESET} (out), 2 VOUT1 (power), 3 GND (power), 4 BYPASS, 5 ~{SHDN2} (in), 6 VOUT2 (power), 7 VIN (power), 8 VDET (power)

## TC1301A-EDAVMF
designator U?
Dual LDO with Microcontroller Active-Low Reset Function, 8-Pin DFN, Extended Temperature
footprint DFN-MF8 (SON, 8-Leads, Body 3x3mm, Pitch 0.65mm, Microchip Recommended)
pins: 1 ~{RESET} (out), 2 VOUT1 (power), 3 GND (power), 4 BYPASS, 5 ~{SHDN2} (in), 6 VOUT2 (power), 7 VIN (power), 8 VDET (power), 9 EP (power)

## TC1301A-EDAVUA
designator U?
Dual LDO with Microcontroller Active-Low Reset Function, 8-Pin MSOP, Extended Temperature
footprint MSOP-UA8_N (TSOP, 8-Leads, Body 3x3mm, Pitch 0.65mm, IPC Medium Density)
footprint MSOP-UA8_L (TSOP, 8-Leads, Body 3x3mm, Pitch 0.65mm, IPC High Density)
footprint MSOP-UA8_M (TSOP, 8-Leads, Body 3x3mm, Pitch 0.65mm, IPC Low Density)
pins: 1 ~{RESET} (out), 2 VOUT1 (power), 3 GND (power), 4 BYPASS, 5 ~{SHDN2} (in), 6 VOUT2 (power), 7 VIN (power), 8 VDET (power)

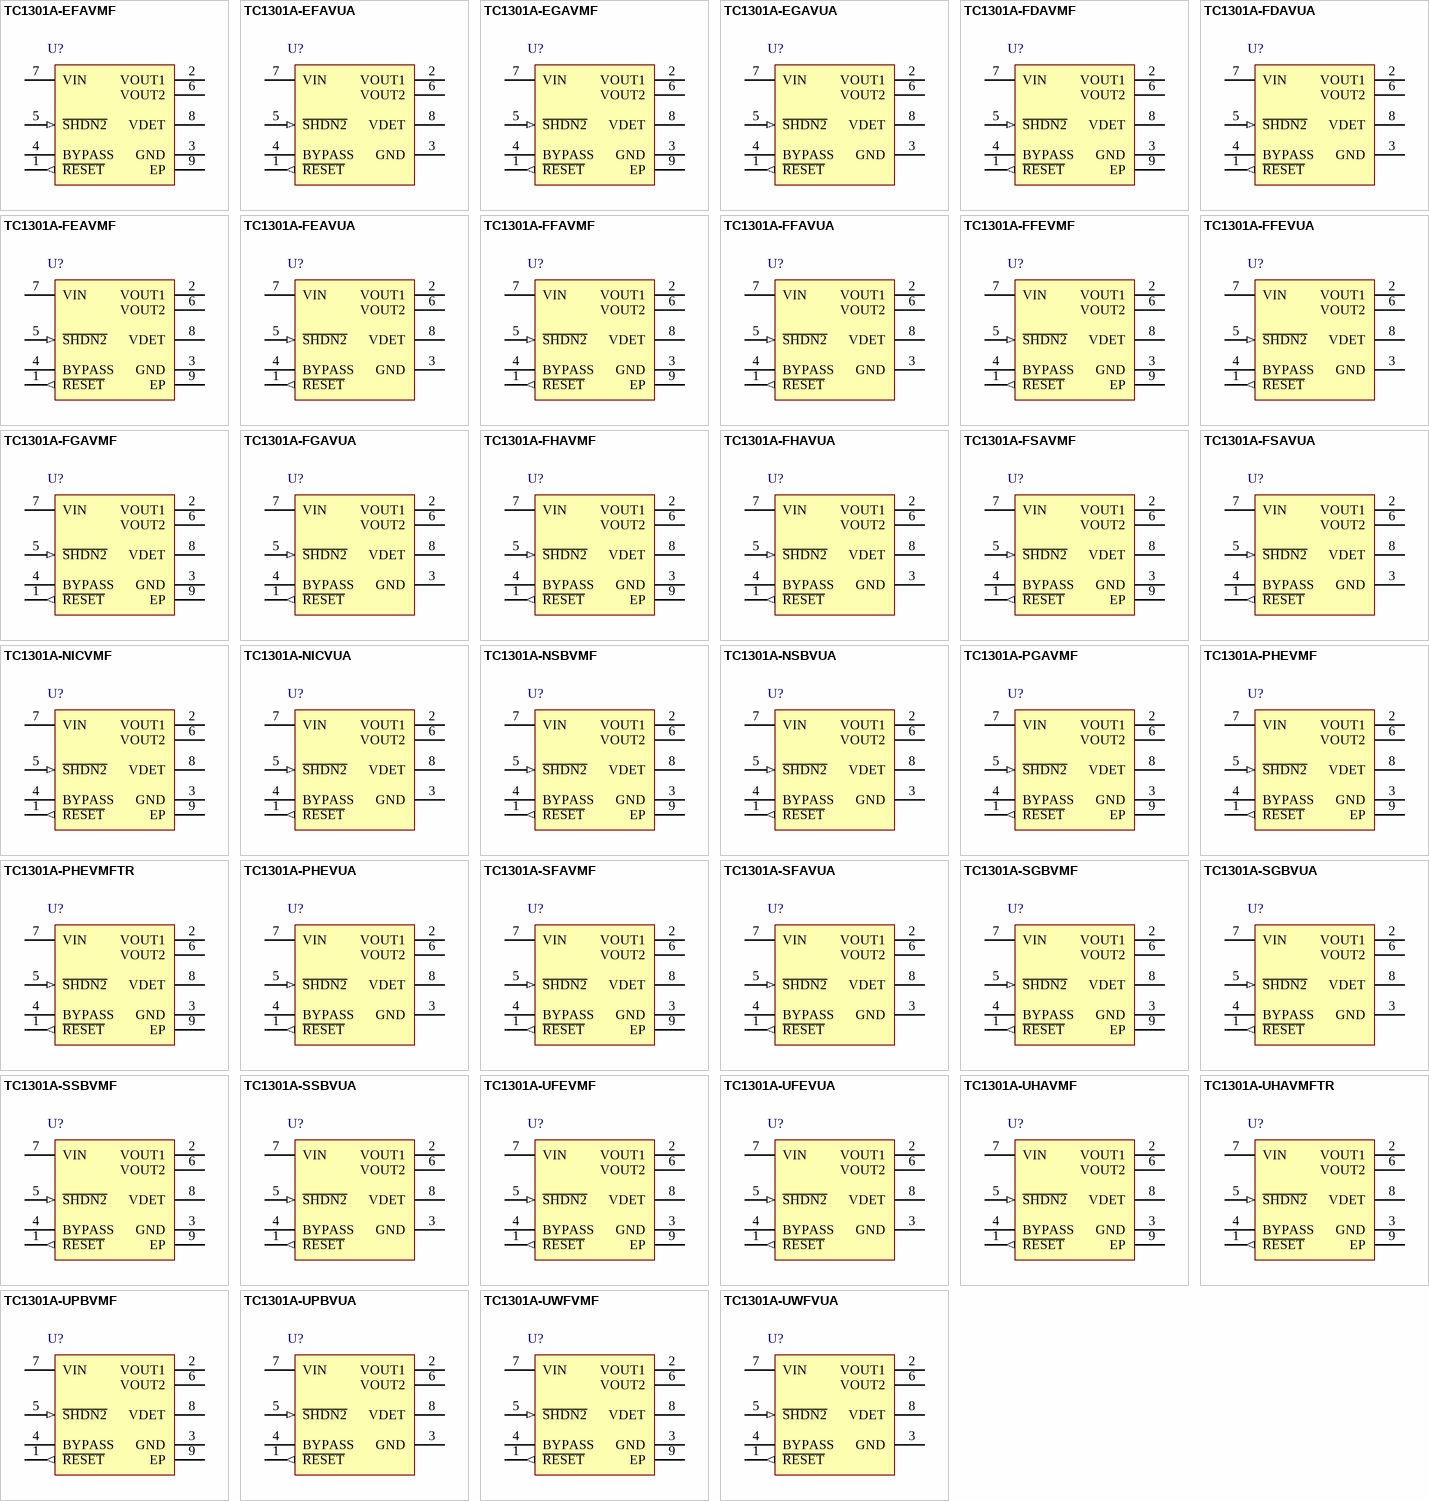
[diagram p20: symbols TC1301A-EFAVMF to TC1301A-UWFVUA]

## TC1301A-EFAVMF
designator U?
Dual LDO with Microcontroller Active-Low Reset Function, 8-Pin DFN, Extended Temperature
footprint DFN-MF8 (SON, 8-Leads, Body 3x3mm, Pitch 0.65mm, Microchip Recommended)
pins: 1 ~{RESET} (out), 2 VOUT1 (power), 3 GND (power), 4 BYPASS, 5 ~{SHDN2} (in), 6 VOUT2 (power), 7 VIN (power), 8 VDET (power), 9 EP (power)

## TC1301A-EFAVUA
designator U?
Dual LDO with Microcontroller Active-Low Reset Function, 8-Pin MSOP, Extended Temperature
footprint MSOP-UA8_N (TSOP, 8-Leads, Body 3x3mm, Pitch 0.65mm, IPC Medium Density)
footprint MSOP-UA8_L (TSOP, 8-Leads, Body 3x3mm, Pitch 0.65mm, IPC High Density)
footprint MSOP-UA8_M (TSOP, 8-Leads, Body 3x3mm, Pitch 0.65mm, IPC Low Density)
pins: 1 ~{RESET} (out), 2 VOUT1 (power), 3 GND (power), 4 BYPASS, 5 ~{SHDN2} (in), 6 VOUT2 (power), 7 VIN (power), 8 VDET (power)

## TC1301A-EGAVMF
designator U?
Dual LDO with Microcontroller Active-Low Reset Function, 8-Pin DFN, Extended Temperature
footprint DFN-MF8 (SON, 8-Leads, Body 3x3mm, Pitch 0.65mm, Microchip Recommended)
pins: 1 ~{RESET} (out), 2 VOUT1 (power), 3 GND (power), 4 BYPASS, 5 ~{SHDN2} (in), 6 VOUT2 (power), 7 VIN (power), 8 VDET (power), 9 EP (power)

## TC1301A-EGAVUA
designator U?
Dual LDO with Microcontroller Active-Low Reset Function, 8-Pin MSOP, Extended Temperature
footprint MSOP-UA8_N (TSOP, 8-Leads, Body 3x3mm, Pitch 0.65mm, IPC Medium Density)
footprint MSOP-UA8_L (TSOP, 8-Leads, Body 3x3mm, Pitch 0.65mm, IPC High Density)
footprint MSOP-UA8_M (TSOP, 8-Leads, Body 3x3mm, Pitch 0.65mm, IPC Low Density)
pins: 1 ~{RESET} (out), 2 VOUT1 (power), 3 GND (power), 4 BYPASS, 5 ~{SHDN2} (in), 6 VOUT2 (power), 7 VIN (power), 8 VDET (power)

## TC1301A-FDAVMF
designator U?
Dual LDO with Microcontroller Active-Low Reset Function, 8-Pin DFN, Extended Temperature
footprint DFN-MF8 (SON, 8-Leads, Body 3x3mm, Pitch 0.65mm, Microchip Recommended)
pins: 1 ~{RESET} (out), 2 VOUT1 (power), 3 GND (power), 4 BYPASS, 5 ~{SHDN2} (in), 6 VOUT2 (power), 7 VIN (power), 8 VDET (power), 9 EP (power)

## TC1301A-FDAVUA
designator U?
Dual LDO with Microcontroller Active-Low Reset Function, 8-Pin MSOP, Extended Temperature
footprint MSOP-UA8_N (TSOP, 8-Leads, Body 3x3mm, Pitch 0.65mm, IPC Medium Density)
footprint MSOP-UA8_L (TSOP, 8-Leads, Body 3x3mm, Pitch 0.65mm, IPC High Density)
footprint MSOP-UA8_M (TSOP, 8-Leads, Body 3x3mm, Pitch 0.65mm, IPC Low Density)
pins: 1 ~{RESET} (out), 2 VOUT1 (power), 3 GND (power), 4 BYPASS, 5 ~{SHDN2} (in), 6 VOUT2 (power), 7 VIN (power), 8 VDET (power)

## TC1301A-FEAVMF
designator U?
Dual LDO with Microcontroller Active-Low Reset Function, 8-Pin DFN, Extended Temperature
footprint DFN-MF8 (SON, 8-Leads, Body 3x3mm, Pitch 0.65mm, Microchip Recommended)
pins: 1 ~{RESET} (out), 2 VOUT1 (power), 3 GND (power), 4 BYPASS, 5 ~{SHDN2} (in), 6 VOUT2 (power), 7 VIN (power), 8 VDET (power), 9 EP (power)

## TC1301A-FEAVUA
designator U?
Dual LDO with Microcontroller Active-Low Reset Function, 8-Pin MSOP, Extended Temperature
footprint MSOP-UA8_N (TSOP, 8-Leads, Body 3x3mm, Pitch 0.65mm, IPC Medium Density)
footprint MSOP-UA8_L (TSOP, 8-Leads, Body 3x3mm, Pitch 0.65mm, IPC High Density)
footprint MSOP-UA8_M (TSOP, 8-Leads, Body 3x3mm, Pitch 0.65mm, IPC Low Density)
pins: 1 ~{RESET} (out), 2 VOUT1 (power), 3 GND (power), 4 BYPASS, 5 ~{SHDN2} (in), 6 VOUT2 (power), 7 VIN (power), 8 VDET (power)

## TC1301A-FFAVMF
designator U?
Dual LDO with Microcontroller Active-Low Reset Function, 8-Pin DFN, Extended Temperature
footprint DFN-MF8 (SON, 8-Leads, Body 3x3mm, Pitch 0.65mm, Microchip Recommended)
pins: 1 ~{RESET} (out), 2 VOUT1 (power), 3 GND (power), 4 BYPASS, 5 ~{SHDN2} (in), 6 VOUT2 (power), 7 VIN (power), 8 VDET (power), 9 EP (power)

## TC1301A-FFAVUA
designator U?
Dual LDO with Microcontroller Active-Low Reset Function, 8-Pin MSOP, Extended Temperature
footprint MSOP-UA8_N (TSOP, 8-Leads, Body 3x3mm, Pitch 0.65mm, IPC Medium Density)
footprint MSOP-UA8_L (TSOP, 8-Leads, Body 3x3mm, Pitch 0.65mm, IPC High Density)
footprint MSOP-UA8_M (TSOP, 8-Leads, Body 3x3mm, Pitch 0.65mm, IPC Low Density)
pins: 1 ~{RESET} (out), 2 VOUT1 (power), 3 GND (power), 4 BYPASS, 5 ~{SHDN2} (in), 6 VOUT2 (power), 7 VIN (power), 8 VDET (power)

## TC1301A-FFEVMF
designator U?
Dual LDO with Microcontroller Active-Low Reset Function, 8-Pin DFN, Extended Temperature
footprint DFN-MF8 (SON, 8-Leads, Body 3x3mm, Pitch 0.65mm, Microchip Recommended)
pins: 1 ~{RESET} (out), 2 VOUT1 (power), 3 GND (power), 4 BYPASS, 5 ~{SHDN2} (in), 6 VOUT2 (power), 7 VIN (power), 8 VDET (power), 9 EP (power)

## TC1301A-FFEVUA
designator U?
Dual LDO with Microcontroller Active-Low Reset Function, 8-Pin MSOP, Extended Temperature
footprint MSOP-UA8_N (TSOP, 8-Leads, Body 3x3mm, Pitch 0.65mm, IPC Medium Density)
footprint MSOP-UA8_L (TSOP, 8-Leads, Body 3x3mm, Pitch 0.65mm, IPC High Density)
footprint MSOP-UA8_M (TSOP, 8-Leads, Body 3x3mm, Pitch 0.65mm, IPC Low Density)
pins: 1 ~{RESET} (out), 2 VOUT1 (power), 3 GND (power), 4 BYPASS, 5 ~{SHDN2} (in), 6 VOUT2 (power), 7 VIN (power), 8 VDET (power)

## TC1301A-FGAVMF
designator U?
Dual LDO with Microcontroller Active-Low Reset Function, 8-Pin DFN, Extended Temperature
footprint DFN-MF8 (SON, 8-Leads, Body 3x3mm, Pitch 0.65mm, Microchip Recommended)
pins: 1 ~{RESET} (out), 2 VOUT1 (power), 3 GND (power), 4 BYPASS, 5 ~{SHDN2} (in), 6 VOUT2 (power), 7 VIN (power), 8 VDET (power), 9 EP (power)

## TC1301A-FGAVUA
designator U?
Dual LDO with Microcontroller Active-Low Reset Function, 8-Pin MSOP, Extended Temperature
footprint MSOP-UA8_N (TSOP, 8-Leads, Body 3x3mm, Pitch 0.65mm, IPC Medium Density)
footprint MSOP-UA8_L (TSOP, 8-Leads, Body 3x3mm, Pitch 0.65mm, IPC High Density)
footprint MSOP-UA8_M (TSOP, 8-Leads, Body 3x3mm, Pitch 0.65mm, IPC Low Density)
pins: 1 ~{RESET} (out), 2 VOUT1 (power), 3 GND (power), 4 BYPASS, 5 ~{SHDN2} (in), 6 VOUT2 (power), 7 VIN (power), 8 VDET (power)

## TC1301A-FHAVMF
designator U?
Dual LDO with Microcontroller Active-Low Reset Function, 8-Pin DFN, Extended Temperature
footprint DFN-MF8 (SON, 8-Leads, Body 3x3mm, Pitch 0.65mm, Microchip Recommended)
pins: 1 ~{RESET} (out), 2 VOUT1 (power), 3 GND (power), 4 BYPASS, 5 ~{SHDN2} (in), 6 VOUT2 (power), 7 VIN (power), 8 VDET (power), 9 EP (power)

## TC1301A-FHAVUA
designator U?
Dual LDO with Microcontroller Active-Low Reset Function, 8-Pin MSOP, Extended Temperature
footprint MSOP-UA8_N (TSOP, 8-Leads, Body 3x3mm, Pitch 0.65mm, IPC Medium Density)
footprint MSOP-UA8_L (TSOP, 8-Leads, Body 3x3mm, Pitch 0.65mm, IPC High Density)
footprint MSOP-UA8_M (TSOP, 8-Leads, Body 3x3mm, Pitch 0.65mm, IPC Low Density)
pins: 1 ~{RESET} (out), 2 VOUT1 (power), 3 GND (power), 4 BYPASS, 5 ~{SHDN2} (in), 6 VOUT2 (power), 7 VIN (power), 8 VDET (power)

## TC1301A-FSAVMF
designator U?
Dual LDO with Microcontroller Active-Low Reset Function, 8-Pin DFN, Extended Temperature
footprint DFN-MF8 (SON, 8-Leads, Body 3x3mm, Pitch 0.65mm, Microchip Recommended)
pins: 1 ~{RESET} (out), 2 VOUT1 (power), 3 GND (power), 4 BYPASS, 5 ~{SHDN2} (in), 6 VOUT2 (power), 7 VIN (power), 8 VDET (power), 9 EP (power)

## TC1301A-FSAVUA
designator U?
Dual LDO with Microcontroller Active-Low Reset Function, 8-Pin MSOP, Extended Temperature
footprint MSOP-UA8_N (TSOP, 8-Leads, Body 3x3mm, Pitch 0.65mm, IPC Medium Density)
footprint MSOP-UA8_L (TSOP, 8-Leads, Body 3x3mm, Pitch 0.65mm, IPC High Density)
footprint MSOP-UA8_M (TSOP, 8-Leads, Body 3x3mm, Pitch 0.65mm, IPC Low Density)
pins: 1 ~{RESET} (out), 2 VOUT1 (power), 3 GND (power), 4 BYPASS, 5 ~{SHDN2} (in), 6 VOUT2 (power), 7 VIN (power), 8 VDET (power)

## TC1301A-NICVMF
designator U?
Dual LDO with Microcontroller Active-Low Reset Function, 8-Pin DFN, Extended Temperature
footprint DFN-MF8 (SON, 8-Leads, Body 3x3mm, Pitch 0.65mm, Microchip Recommended)
pins: 1 ~{RESET} (out), 2 VOUT1 (power), 3 GND (power), 4 BYPASS, 5 ~{SHDN2} (in), 6 VOUT2 (power), 7 VIN (power), 8 VDET (power), 9 EP (power)

## TC1301A-NICVUA
designator U?
Dual LDO with Microcontroller Active-Low Reset Function, 8-Pin MSOP, Extended Temperature
footprint MSOP-UA8_N (TSOP, 8-Leads, Body 3x3mm, Pitch 0.65mm, IPC Medium Density)
footprint MSOP-UA8_L (TSOP, 8-Leads, Body 3x3mm, Pitch 0.65mm, IPC High Density)
footprint MSOP-UA8_M (TSOP, 8-Leads, Body 3x3mm, Pitch 0.65mm, IPC Low Density)
pins: 1 ~{RESET} (out), 2 VOUT1 (power), 3 GND (power), 4 BYPASS, 5 ~{SHDN2} (in), 6 VOUT2 (power), 7 VIN (power), 8 VDET (power)

## TC1301A-NSBVMF
designator U?
Dual LDO with Microcontroller Active-Low Reset Function, 8-Pin DFN, Extended Temperature
footprint DFN-MF8 (SON, 8-Leads, Body 3x3mm, Pitch 0.65mm, Microchip Recommended)
pins: 1 ~{RESET} (out), 2 VOUT1 (power), 3 GND (power), 4 BYPASS, 5 ~{SHDN2} (in), 6 VOUT2 (power), 7 VIN (power), 8 VDET (power), 9 EP (power)

## TC1301A-NSBVUA
designator U?
Dual LDO with Microcontroller Active-Low Reset Function, 8-Pin MSOP, Extended Temperature
footprint MSOP-UA8_N (TSOP, 8-Leads, Body 3x3mm, Pitch 0.65mm, IPC Medium Density)
footprint MSOP-UA8_L (TSOP, 8-Leads, Body 3x3mm, Pitch 0.65mm, IPC High Density)
footprint MSOP-UA8_M (TSOP, 8-Leads, Body 3x3mm, Pitch 0.65mm, IPC Low Density)
pins: 1 ~{RESET} (out), 2 VOUT1 (power), 3 GND (power), 4 BYPASS, 5 ~{SHDN2} (in), 6 VOUT2 (power), 7 VIN (power), 8 VDET (power)

## TC1301A-PGAVMF
designator U?
Dual LDO with Microcontroller Active-Low Reset Function, 8-Pin DFN, Extended Temperature
footprint DFN-MF8 (SON, 8-Leads, Body 3x3mm, Pitch 0.65mm, Microchip Recommended)
pins: 1 ~{RESET} (out), 2 VOUT1 (power), 3 GND (power), 4 BYPASS, 5 ~{SHDN2} (in), 6 VOUT2 (power), 7 VIN (power), 8 VDET (power), 9 EP (power)

## TC1301A-PHEVMF
designator U?
Dual LDO with Microcontroller Active-Low Reset Function, 8-Pin DFN, Extended Temperature
footprint DFN-MF8 (SON, 8-Leads, Body 3x3mm, Pitch 0.65mm, Microchip Recommended)
pins: 1 ~{RESET} (out), 2 VOUT1 (power), 3 GND (power), 4 BYPASS, 5 ~{SHDN2} (in), 6 VOUT2 (power), 7 VIN (power), 8 VDET (power), 9 EP (power)

## TC1301A-PHEVMFTR
designator U?
Dual LDO with Microcontroller Active-Low Reset Function, 8-Pin DFN, Extended Temperature, Tape and Reel
footprint DFN-MF8 (SON, 8-Leads, Body 3x3mm, Pitch 0.65mm, Microchip Recommended)
pins: 1 ~{RESET} (out), 2 VOUT1 (power), 3 GND (power), 4 BYPASS, 5 ~{SHDN2} (in), 6 VOUT2 (power), 7 VIN (power), 8 VDET (power), 9 EP (power)

## TC1301A-PHEVUA
designator U?
Dual LDO with Microcontroller Active-Low Reset Function, 8-Pin MSOP, Extended Temperature
footprint MSOP-UA8_N (TSOP, 8-Leads, Body 3x3mm, Pitch 0.65mm, IPC Medium Density)
footprint MSOP-UA8_L (TSOP, 8-Leads, Body 3x3mm, Pitch 0.65mm, IPC High Density)
footprint MSOP-UA8_M (TSOP, 8-Leads, Body 3x3mm, Pitch 0.65mm, IPC Low Density)
pins: 1 ~{RESET} (out), 2 VOUT1 (power), 3 GND (power), 4 BYPASS, 5 ~{SHDN2} (in), 6 VOUT2 (power), 7 VIN (power), 8 VDET (power)

## TC1301A-SFAVMF
designator U?
Dual LDO with Microcontroller Active-Low Reset Function, 8-Pin DFN, Extended Temperature
footprint DFN-MF8 (SON, 8-Leads, Body 3x3mm, Pitch 0.65mm, Microchip Recommended)
pins: 1 ~{RESET} (out), 2 VOUT1 (power), 3 GND (power), 4 BYPASS, 5 ~{SHDN2} (in), 6 VOUT2 (power), 7 VIN (power), 8 VDET (power), 9 EP (power)

## TC1301A-SFAVUA
designator U?
Dual LDO with Microcontroller Active-Low Reset Function, 8-Pin MSOP, Extended Temperature
footprint MSOP-UA8_N (TSOP, 8-Leads, Body 3x3mm, Pitch 0.65mm, IPC Medium Density)
footprint MSOP-UA8_L (TSOP, 8-Leads, Body 3x3mm, Pitch 0.65mm, IPC High Density)
footprint MSOP-UA8_M (TSOP, 8-Leads, Body 3x3mm, Pitch 0.65mm, IPC Low Density)
pins: 1 ~{RESET} (out), 2 VOUT1 (power), 3 GND (power), 4 BYPASS, 5 ~{SHDN2} (in), 6 VOUT2 (power), 7 VIN (power), 8 VDET (power)

## TC1301A-SGBVMF
designator U?
Dual LDO with Microcontroller Active-Low Reset Function, 8-Pin DFN, Extended Temperature
footprint DFN-MF8 (SON, 8-Leads, Body 3x3mm, Pitch 0.65mm, Microchip Recommended)
pins: 1 ~{RESET} (out), 2 VOUT1 (power), 3 GND (power), 4 BYPASS, 5 ~{SHDN2} (in), 6 VOUT2 (power), 7 VIN (power), 8 VDET (power), 9 EP (power)

## TC1301A-SGBVUA
designator U?
Dual LDO with Microcontroller Active-Low Reset Function, 8-Pin MSOP, Extended Temperature
footprint MSOP-UA8_N (TSOP, 8-Leads, Body 3x3mm, Pitch 0.65mm, IPC Medium Density)
footprint MSOP-UA8_L (TSOP, 8-Leads, Body 3x3mm, Pitch 0.65mm, IPC High Density)
footprint MSOP-UA8_M (TSOP, 8-Leads, Body 3x3mm, Pitch 0.65mm, IPC Low Density)
pins: 1 ~{RESET} (out), 2 VOUT1 (power), 3 GND (power), 4 BYPASS, 5 ~{SHDN2} (in), 6 VOUT2 (power), 7 VIN (power), 8 VDET (power)

## TC1301A-SSBVMF
designator U?
Dual LDO with Microcontroller Active-Low Reset Function, 8-Pin DFN, Extended Temperature
footprint DFN-MF8 (SON, 8-Leads, Body 3x3mm, Pitch 0.65mm, Microchip Recommended)
pins: 1 ~{RESET} (out), 2 VOUT1 (power), 3 GND (power), 4 BYPASS, 5 ~{SHDN2} (in), 6 VOUT2 (power), 7 VIN (power), 8 VDET (power), 9 EP (power)

## TC1301A-SSBVUA
designator U?
Dual LDO with Microcontroller Active-Low Reset Function, 8-Pin MSOP, Extended Temperature
footprint MSOP-UA8_N (TSOP, 8-Leads, Body 3x3mm, Pitch 0.65mm, IPC Medium Density)
footprint MSOP-UA8_L (TSOP, 8-Leads, Body 3x3mm, Pitch 0.65mm, IPC High Density)
footprint MSOP-UA8_M (TSOP, 8-Leads, Body 3x3mm, Pitch 0.65mm, IPC Low Density)
pins: 1 ~{RESET} (out), 2 VOUT1 (power), 3 GND (power), 4 BYPASS, 5 ~{SHDN2} (in), 6 VOUT2 (power), 7 VIN (power), 8 VDET (power)

## TC1301A-UFEVMF
designator U?
Dual LDO with Microcontroller Active-Low Reset Function, 8-Pin DFN, Extended Temperature
footprint DFN-MF8 (SON, 8-Leads, Body 3x3mm, Pitch 0.65mm, Microchip Recommended)
pins: 1 ~{RESET} (out), 2 VOUT1 (power), 3 GND (power), 4 BYPASS, 5 ~{SHDN2} (in), 6 VOUT2 (power), 7 VIN (power), 8 VDET (power), 9 EP (power)

## TC1301A-UFEVUA
designator U?
Dual LDO with Microcontroller Active-Low Reset Function, 8-Pin MSOP, Extended Temperature
footprint MSOP-UA8_N (TSOP, 8-Leads, Body 3x3mm, Pitch 0.65mm, IPC Medium Density)
footprint MSOP-UA8_L (TSOP, 8-Leads, Body 3x3mm, Pitch 0.65mm, IPC High Density)
footprint MSOP-UA8_M (TSOP, 8-Leads, Body 3x3mm, Pitch 0.65mm, IPC Low Density)
pins: 1 ~{RESET} (out), 2 VOUT1 (power), 3 GND (power), 4 BYPASS, 5 ~{SHDN2} (in), 6 VOUT2 (power), 7 VIN (power), 8 VDET (power)

## TC1301A-UHAVMF
designator U?
Dual LDO with Microcontroller Active-Low Reset Function, 8-Pin DFN, Extended Temperature
footprint DFN-MF8 (SON, 8-Leads, Body 3x3mm, Pitch 0.65mm, Microchip Recommended)
pins: 1 ~{RESET} (out), 2 VOUT1 (power), 3 GND (power), 4 BYPASS, 5 ~{SHDN2} (in), 6 VOUT2 (power), 7 VIN (power), 8 VDET (power), 9 EP (power)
